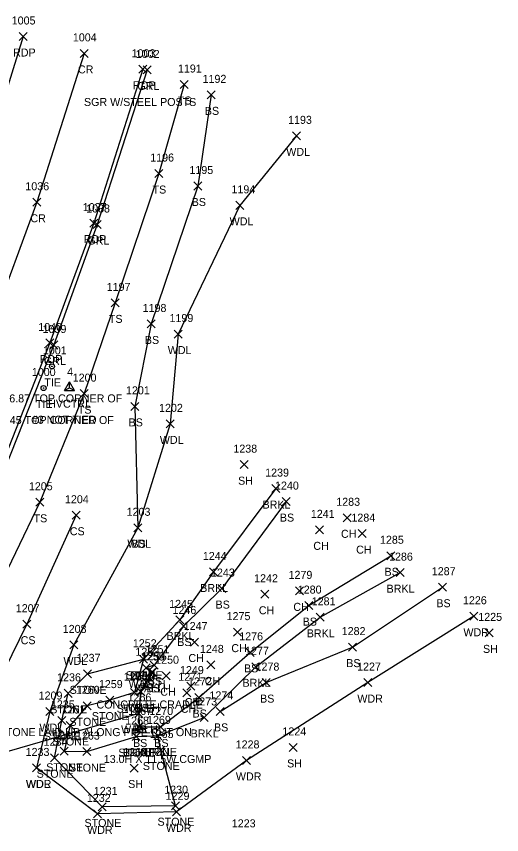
# Model space of a CAD drawing. Extents: x 1599840 to 1601211, y 518904 to 521989.
# Drawn here: x 1600924.1 to 1601045.4, y 521308.1 to 521512.5 of the extents above; entities that cross this region are included whole.
import ezdxf

# ---------------------------------------------------------------- set-up
doc = ezdxf.new("R2010")
doc.units = 0
for name, color, linetype in [('C_A', 7, 'Continuous'), ('C_C', 7, 'Continuous'), ('C_I', 7, 'Continuous'), ('CBP', 7, 'Continuous'), ('CPSM', 7, 'Continuous'), ('D_A', 7, 'Continuous'), ('D_C', 7, 'Continuous'), ('D_I', 7, 'Continuous'), ('D_TIC', 7, 'Continuous'), ('DCP', 7, 'Continuous'), ('DHW', 7, 'Continuous'), ('L_A', 7, 'Continuous'), ('L_C', 7, 'Continuous'), ('L_I', 7, 'Continuous'), ('L_TIC', 7, 'Continuous'), ('LASF', 7, 'Continuous'), ('LAWA', 7, 'Continuous'), ('LAWE', 7, 'Continuous'), ('LELB', 7, 'Continuous'), ('P_A', 7, 'Continuous'), ('P_I', 7, 'Continuous'), ('P_TIC', 7, 'Continuous'), ('PET', 7, 'Continuous'), ('PRC', 7, 'Continuous'), ('R_A', 7, 'Continuous'), ('R_C', 7, 'Continuous'), ('R_I', 7, 'Continuous'), ('R_TIC', 7, 'Continuous'), ('RGR', 7, 'Continuous')]:
    doc.layers.add(name, color=color, linetype=linetype)

msp = doc.modelspace()

# ---------------------------------------------------------------- linework, layer by layer
at = {"layer": 'CBP'}
for centre, radius in [((1600933.05, 521425.11), 0.625), ((1600933.05, 521425.11), 0.0833), ((1600930.95, 521419.7), 0.625), ((1600930.95, 521419.7), 0.0833)]:
    msp.add_circle(centre, radius, dxfattribs=at)
at = {"layer": 'CPSM'}
for p, q in [((1600936.15, 521419.07), (1600937.4, 521421.24)), ((1600938.65, 521419.07), (1600937.4, 521421.24)), ((1600937.4, 521419.79), (1600937.4, 521421.24)), ((1600936.15, 521419.07), (1600937.4, 521419.79)), ((1600936.15, 521419.07), (1600938.65, 521419.07)), ((1600937.4, 521419.79), (1600937.4, 521419.79)), ((1600937.4, 521419.79), (1600938.65, 521419.07))]:
    msp.add_line(p, q, dxfattribs=at)
at = {"layer": 'D_TIC'}
for points in [[(1600955.59, 521348.8), (1600957.59, 521350.8)], [(1600957.59, 521348.8), (1600955.59, 521350.8)], [(1600956.92, 521347.64), (1600958.92, 521349.64)], [(1600958.92, 521347.64), (1600956.92, 521349.64)], [(1600954.19, 521342.91), (1600956.19, 521344.91)], [(1600956.19, 521342.91), (1600954.19, 521344.91)], [(1600953.73, 521337.43), (1600955.73, 521339.43)], [(1600955.73, 521337.43), (1600953.73, 521339.43)], [(1600953.73, 521337.43), (1600955.73, 521339.43)], [(1600955.73, 521337.43), (1600953.73, 521339.43)]]:
    msp.add_lwpolyline(points, dxfattribs=at)
at = {"layer": 'DCP'}
msp.add_lwpolyline([(1600954.73, 521338.43), (1600785.44, 521289.23)], dxfattribs=at)
at = {"layer": 'DHW'}
msp.add_lwpolyline([(1600956.59, 521349.8), (1600957.92, 521348.64), (1600955.19, 521343.91), (1600954.73, 521338.43)], dxfattribs=at)
at = {"layer": 'L_TIC'}
for points in [[(1600965.09, 521494.52), (1600967.09, 521496.52)], [(1600967.09, 521494.52), (1600965.09, 521496.52)], [(1600971.81, 521491.94), (1600973.81, 521493.94)], [(1600973.81, 521491.94), (1600971.81, 521493.94)], [(1600993.18, 521481.7), (1600995.18, 521483.7)], [(1600995.18, 521481.7), (1600993.18, 521483.7)], [(1600958.78, 521472.28), (1600960.78, 521474.28)], [(1600960.78, 521472.28), (1600958.78, 521474.28)], [(1600968.53, 521469.17), (1600970.53, 521471.17)], [(1600970.53, 521469.17), (1600968.53, 521471.17)], [(1600979.04, 521464.34), (1600981.04, 521466.34)], [(1600981.04, 521464.34), (1600979.04, 521466.34)], [(1600947.85, 521439.97), (1600949.85, 521441.97)], [(1600949.85, 521439.97), (1600947.85, 521441.97)], [(1600956.82, 521434.71), (1600958.82, 521436.71)], [(1600958.82, 521434.71), (1600956.82, 521436.71)], [(1600963.56, 521432.18), (1600965.56, 521434.18)], [(1600965.56, 521432.18), (1600963.56, 521434.18)], [(1600940.09, 521417.3), (1600942.09, 521419.3)], [(1600942.09, 521417.3), (1600940.09, 521419.3)], [(1600952.74, 521414.12), (1600954.74, 521416.12)], [(1600954.74, 521414.12), (1600952.74, 521416.12)], [(1600961.58, 521409.75), (1600963.58, 521411.75)], [(1600963.58, 521409.75), (1600961.58, 521411.75)], [(1600980.08, 521399.56), (1600982.08, 521401.56)], [(1600982.08, 521399.56), (1600980.08, 521401.56)], [(1600988.03, 521393.58), (1600990.03, 521395.58)], [(1600990.03, 521393.58), (1600988.03, 521395.58)], [(1600929.04, 521390.16), (1600931.04, 521392.16)], [(1600931.04, 521390.16), (1600929.04, 521392.16)], [(1600990.57, 521390.33), (1600992.57, 521392.33)], [(1600992.57, 521390.33), (1600990.57, 521392.33)], [(1600938.06, 521386.92), (1600940.06, 521388.92)], [(1600940.06, 521386.92), (1600938.06, 521388.92)], [(1601005.79, 521386.28), (1601007.79, 521388.28)], [(1601007.79, 521386.28), (1601005.79, 521388.28)], [(1600953.48, 521383.78), (1600955.48, 521385.78)], [(1600955.48, 521383.78), (1600953.48, 521385.78)], [(1600953.48, 521383.78), (1600955.48, 521385.78)], [(1600955.48, 521383.78), (1600953.48, 521385.78)], [(1600998.88, 521383.27), (1601000.88, 521385.27)], [(1601000.88, 521383.27), (1600998.88, 521385.27)], [(1601009.59, 521382.33), (1601011.59, 521384.33)], [(1601011.59, 521382.33), (1601009.59, 521384.33)], [(1601016.73, 521376.8), (1601018.73, 521378.8)], [(1601018.73, 521376.8), (1601016.73, 521378.8)], [(1600972.45, 521372.75), (1600974.45, 521374.75)], [(1600974.45, 521372.75), (1600972.45, 521374.75)], [(1601019.04, 521372.58), (1601021.04, 521374.58)], [(1601021.04, 521372.58), (1601019.04, 521374.58)], [(1601029.68, 521368.94), (1601031.68, 521370.94)], [(1601031.68, 521368.94), (1601029.68, 521370.94)], [(1600974.49, 521368.6), (1600976.49, 521370.6)], [(1600976.49, 521368.6), (1600974.49, 521370.6)], [(1600985.27, 521367.18), (1600987.27, 521369.18)], [(1600987.27, 521367.18), (1600985.27, 521369.18)], [(1600993.88, 521368.03), (1600995.88, 521370.03)], [(1600995.88, 521368.03), (1600993.88, 521370.03)], [(1600996.25, 521364.35), (1600998.25, 521366.35)], [(1600998.25, 521364.35), (1600996.25, 521366.35)], [(1600964.03, 521360.78), (1600966.03, 521362.78)], [(1600966.03, 521360.78), (1600964.03, 521362.78)], [(1600999.08, 521361.42), (1601001.08, 521363.42)], [(1601001.08, 521361.42), (1600999.08, 521363.42)], [(1601037.52, 521361.68), (1601039.52, 521363.68)], [(1601039.52, 521361.68), (1601037.52, 521363.68)], [(1600925.77, 521359.7), (1600927.77, 521361.7)], [(1600927.77, 521359.7), (1600925.77, 521361.7)], [(1600964.92, 521359.25), (1600966.92, 521361.25)], [(1600966.92, 521359.25), (1600964.92, 521361.25)], [(1600978.38, 521357.72), (1600980.38, 521359.72)], [(1600980.38, 521357.72), (1600978.38, 521359.72)], [(1601041.3, 521357.53), (1601043.3, 521359.53)], [(1601043.3, 521357.53), (1601041.3, 521359.53)], [(1600967.66, 521355.25), (1600969.66, 521357.25)], [(1600969.66, 521355.25), (1600967.66, 521357.25)], [(1600937.5, 521354.53), (1600939.5, 521356.53)], [(1600939.5, 521354.53), (1600937.5, 521356.53)], [(1600981.6, 521352.67), (1600983.6, 521354.67)], [(1600983.6, 521352.67), (1600981.6, 521354.67)], [(1601007.16, 521353.98), (1601009.16, 521355.98)], [(1601009.16, 521353.98), (1601007.16, 521355.98)], [(1600954.94, 521350.95), (1600956.94, 521352.95)], [(1600956.94, 521350.95), (1600954.94, 521352.95)], [(1600954.94, 521350.95), (1600956.94, 521352.95)], [(1600956.94, 521350.95), (1600954.94, 521352.95)], [(1600955.59, 521348.8), (1600957.59, 521350.8)], [(1600957.59, 521348.8), (1600955.59, 521350.8)], [(1600957.57, 521349.46), (1600959.57, 521351.46)], [(1600959.57, 521349.46), (1600957.57, 521351.46)], [(1600971.72, 521349.53), (1600973.72, 521351.53)], [(1600973.72, 521349.53), (1600971.72, 521351.53)], [(1600983.01, 521349.06), (1600985.01, 521351.06)], [(1600985.01, 521349.06), (1600983.01, 521351.06)], [(1600940.92, 521347.3), (1600942.92, 521349.3)], [(1600942.92, 521347.3), (1600940.92, 521349.3)], [(1600957.18, 521347.7), (1600959.18, 521349.7)], [(1600959.18, 521347.7), (1600957.18, 521349.7)], [(1600960.62, 521346.83), (1600962.62, 521348.83)], [(1600962.62, 521346.83), (1600960.62, 521348.83)], [(1600985.62, 521345.11), (1600987.62, 521347.11)], [(1600987.62, 521345.11), (1600985.62, 521347.11)], [(1601011.01, 521345.11), (1601013.01, 521347.11)], [(1601013.01, 521345.11), (1601011.01, 521347.11)], [(1600936.06, 521342.43), (1600938.06, 521344.43)], [(1600938.06, 521342.43), (1600936.06, 521344.43)], [(1600952.67, 521342.61), (1600954.67, 521344.61)], [(1600954.67, 521342.61), (1600952.67, 521344.61)], [(1600954.24, 521342.77), (1600956.24, 521344.77)], [(1600956.24, 521342.77), (1600954.24, 521344.77)], [(1600965.76, 521342.57), (1600967.76, 521344.57)], [(1600967.76, 521342.57), (1600965.76, 521344.57)], [(1600966.74, 521344.24), (1600968.74, 521346.24)], [(1600968.74, 521344.24), (1600966.74, 521346.24)], [(1600946.47, 521340.74), (1600948.47, 521342.74)], [(1600948.47, 521340.74), (1600946.47, 521342.74)], [(1600968.74, 521341.39), (1600970.74, 521343.39)], [(1600970.74, 521341.39), (1600968.74, 521343.39)], [(1600940.84, 521339.31), (1600942.84, 521341.31)], [(1600942.84, 521339.31), (1600940.84, 521341.31)], [(1600931.49, 521337.88), (1600933.49, 521339.88)], [(1600933.49, 521337.88), (1600931.49, 521339.88)], [(1600953.73, 521337.43), (1600955.73, 521339.43)], [(1600955.73, 521337.43), (1600953.73, 521339.43)], [(1600970.06, 521336.4), (1600972.06, 521338.4)], [(1600972.06, 521336.4), (1600970.06, 521338.4)], [(1600974.1, 521337.92), (1600976.1, 521339.92)], [(1600976.1, 521337.92), (1600974.1, 521339.92)], [(1600934.47, 521335.68), (1600936.47, 521337.68)], [(1600936.47, 521335.68), (1600934.47, 521337.68)], [(1600936.57, 521334.4), (1600938.57, 521336.4)], [(1600938.57, 521334.4), (1600936.57, 521336.4)], [(1600953.86, 521334.03), (1600955.86, 521336.03)], [(1600955.86, 521334.03), (1600953.86, 521336.03)], [(1600959.17, 521334.02), (1600961.17, 521336.02)], [(1600961.17, 521334.02), (1600959.17, 521336.02)], [(1600953.08, 521331.61), (1600955.08, 521333.61)], [(1600955.08, 521331.61), (1600953.08, 521333.61)], [(1600953.08, 521331.61), (1600955.08, 521333.61)], [(1600955.08, 521331.61), (1600953.08, 521333.61)], [(1600958.54, 521331.8), (1600960.54, 521333.8)], [(1600960.54, 521331.8), (1600958.54, 521333.8)], [(1600958.54, 521331.8), (1600960.54, 521333.8)], [(1600960.54, 521331.8), (1600958.54, 521333.8)], [(1600959.22, 521328.27), (1600961.22, 521330.27)], [(1600961.22, 521328.27), (1600959.22, 521330.27)], [(1600992.34, 521328.92), (1600994.34, 521330.92)], [(1600994.34, 521328.92), (1600992.34, 521330.92)], [(1600932.66, 521326.34), (1600934.66, 521328.34)], [(1600934.66, 521326.34), (1600932.66, 521328.34)], [(1600935.06, 521327.96), (1600937.06, 521329.96)], [(1600937.06, 521327.96), (1600935.06, 521329.96)], [(1600940.77, 521327.87), (1600942.77, 521329.87)], [(1600942.77, 521327.87), (1600940.77, 521329.87)], [(1600980.65, 521325.67), (1600982.65, 521327.67)], [(1600982.65, 521325.67), (1600980.65, 521327.67)], [(1600928.15, 521323.79), (1600930.15, 521325.79)], [(1600930.15, 521323.79), (1600928.15, 521325.79)], [(1600928.15, 521323.79), (1600930.15, 521325.79)], [(1600930.15, 521323.79), (1600928.15, 521325.79)], [(1600952.6, 521323.77), (1600954.6, 521325.77)], [(1600954.6, 521323.77), (1600952.6, 521325.77)], [(1600944.62, 521314.06), (1600946.62, 521316.06)], [(1600946.62, 521314.06), (1600944.62, 521316.06)], [(1600962.88, 521314.35), (1600964.88, 521316.35)], [(1600964.88, 521314.35), (1600962.88, 521316.35)], [(1600962.88, 521314.35), (1600964.88, 521316.35)], [(1600964.88, 521314.35), (1600962.88, 521316.35)], [(1600943.46, 521312.31), (1600945.46, 521314.31)], [(1600945.46, 521312.31), (1600943.46, 521314.31)], [(1600963.17, 521312.83), (1600965.17, 521314.83)], [(1600965.17, 521312.83), (1600963.17, 521314.83)]]:
    msp.add_lwpolyline(points, dxfattribs=at)
at = {"layer": 'LASF'}
for points in [[(1600963.88, 521315.35), (1600945.62, 521315.06), (1600933.66, 521327.34), (1600935.47, 521336.68), (1600937.06, 521343.43), (1600941.92, 521348.3), (1600955.94, 521351.95), (1600953.67, 521343.61), (1600947.47, 521341.74), (1600941.84, 521340.31), (1600937.57, 521335.4), (1600936.06, 521328.96), (1600941.77, 521328.87), (1600954.08, 521332.61)], [(1600963.88, 521315.35), (1600960.22, 521329.27), (1600959.54, 521332.8)]]:
    msp.add_lwpolyline(points, dxfattribs=at)
at = {"layer": 'LAWA'}
for points in [[(1600994.18, 521482.7), (1600980.04, 521465.34), (1600964.56, 521433.18), (1600962.58, 521410.75), (1600954.48, 521384.78), (1600938.5, 521355.53), (1600932.49, 521338.88), (1600929.15, 521324.79)], [(1601038.52, 521362.68), (1601012.01, 521346.11), (1600981.65, 521326.67), (1600964.17, 521313.83), (1600944.46, 521313.31), (1600929.15, 521324.79)]]:
    msp.add_lwpolyline(points, dxfattribs=at)
at = {"layer": 'LAWE'}
for points in [[(1600989.03, 521394.58), (1600973.45, 521373.75), (1600965.03, 521361.78), (1600955.94, 521351.95)], [(1600954.08, 521332.61), (1600959.54, 521332.8), (1600971.06, 521337.4), (1600984.01, 521350.06), (1601000.08, 521362.42), (1601020.04, 521373.58)]]:
    msp.add_lwpolyline(points, dxfattribs=at)
at = {"layer": 'LELB'}
for points in [[(1600966.09, 521495.52), (1600959.78, 521473.28), (1600948.85, 521440.97), (1600941.09, 521418.3), (1600930.04, 521391.16), (1600917.79, 521365.83), (1600907.01, 521343.38), (1600893.45, 521320.99), (1600884.03, 521297.59), (1600887.61, 521294.19)], [(1600972.81, 521492.94), (1600969.53, 521470.17), (1600957.82, 521435.71), (1600953.74, 521415.12), (1600954.48, 521384.78)], [(1600991.57, 521391.33), (1600975.49, 521369.6), (1600965.92, 521360.25), (1600958.57, 521350.46), (1600956.59, 521349.8), (1600958.18, 521348.7), (1600955.24, 521343.77), (1600954.73, 521338.43), (1600954.86, 521335.03), (1600960.17, 521335.02), (1600969.74, 521342.39), (1600982.6, 521353.67), (1600997.25, 521365.35), (1601017.73, 521377.8)], [(1600939.06, 521387.92), (1600926.77, 521360.7), (1600917.25, 521341.48)], [(1600975.1, 521338.92), (1600986.62, 521346.11), (1601008.16, 521354.98), (1601030.68, 521369.94)]]:
    msp.add_lwpolyline(points, dxfattribs=at)
at = {"layer": 'P_TIC'}
for points in [[(1600924.83, 521506.52), (1600926.83, 521508.52)], [(1600926.83, 521506.52), (1600924.83, 521508.52)], [(1600940.11, 521502.3), (1600942.11, 521504.3)], [(1600942.11, 521502.3), (1600940.11, 521504.3)], [(1600954.79, 521498.34), (1600956.79, 521500.34)], [(1600956.79, 521498.34), (1600954.79, 521500.34)], [(1600928.22, 521465.1), (1600930.22, 521467.1)], [(1600930.22, 521465.1), (1600928.22, 521467.1)], [(1600942.51, 521459.9), (1600944.51, 521461.9)], [(1600944.51, 521459.9), (1600942.51, 521461.9)], [(1600931.49, 521429.95), (1600933.49, 521431.95)], [(1600933.49, 521429.95), (1600931.49, 521431.95)]]:
    msp.add_lwpolyline(points, dxfattribs=at)
at = {"layer": 'PET'}
for points in [[(1600925.83, 521507.52), (1600915.18, 521473.31), (1600903.26, 521440.28), (1600887.48, 521401.44), (1600873.35, 521370.15), (1600860.38, 521343.64), (1600847.93, 521319.69), (1600844.65, 521313.14), (1600836.72, 521299.9), (1600818.79, 521271.51), (1600793.69, 521233.92), (1600774.49, 521208.06), (1600757.09, 521185.54), (1600730.91, 521154.49)], [(1600955.79, 521499.34), (1600943.51, 521460.9), (1600932.49, 521430.95), (1600915.63, 521388.21), (1600902.46, 521359.92), (1600888.21, 521330.27), (1600876.23, 521308.06), (1600874.78, 521305.59), (1600851.3, 521265.61), (1600837.44, 521243.85), (1600825.08, 521225.62), (1600799.95, 521190.82), (1600794.12, 521183.15), (1600773.8, 521157.79), (1600751.79, 521131.81)]]:
    msp.add_lwpolyline(points, dxfattribs=at)
at = {"layer": 'PRC'}
msp.add_lwpolyline([(1600941.11, 521503.3), (1600929.22, 521466.1), (1600917.95, 521435.49), (1600901.05, 521394.76), (1600888.43, 521365.83), (1600873.97, 521336.55), (1600862.78, 521315.41), (1600848.88, 521291.08), (1600831.54, 521262.94), (1600805.42, 521224.44), (1600786.95, 521198.81), (1600768.67, 521175.32), (1600742.32, 521144.02)], dxfattribs=at)
at = {"layer": 'R_TIC'}
for points in [[(1600955.84, 521498.16), (1600957.84, 521500.16)], [(1600957.84, 521498.16), (1600955.84, 521500.16)], [(1600943.35, 521459.55), (1600945.35, 521461.55)], [(1600945.35, 521459.55), (1600943.35, 521461.55)], [(1600932.48, 521429.45), (1600934.48, 521431.45)], [(1600934.48, 521429.45), (1600932.48, 521431.45)]]:
    msp.add_lwpolyline(points, dxfattribs=at)
at = {"layer": 'RGR'}
msp.add_lwpolyline([(1600956.84, 521499.16), (1600944.35, 521460.55), (1600933.48, 521430.45), (1600916.49, 521387.81), (1600903.42, 521359.61), (1600888.96, 521329.85), (1600882.66, 521317.57), (1600880.82, 521311.64), (1600881.59, 521304.98)], dxfattribs=at)

# ---------------------------------------------------------------- texts
at = {"layer": 'C_A'}
for s, p in [('TIE', (1600931.13, 521420.11)), ('TIE', (1600929.03, 521414.7)), ('HVCTRL', (1600932.09, 521414.79))]:
    msp.add_text(s, height=2, dxfattribs=at).set_placement(p)
at = {"layer": 'C_C'}
for s, p in [('TIE DIST=6.87 TOP CORNER OF', (1600909.81, 521416.11)), ('TIE DIST=6.45 TOP CORNER OF', (1600907.71, 521410.7)), ('#3 NOT TIED', (1600928.01, 521410.79))]:
    msp.add_text(s, height=2, dxfattribs=at).set_placement(p)
at = {"layer": 'C_I'}
for s, p in [('1001', (1600930.77, 521428.11)), ('1000', (1600928.01, 521422.7)), ('4', (1600936.83, 521422.79))]:
    msp.add_text(s, height=2, dxfattribs=at).set_placement(p)
at = {"layer": 'D_A'}
for s, p in [('WALLH', (1600952.18, 521344.8)), ('WALLH', (1600953.51, 521343.64)), ('WALLH', (1600950.78, 521338.91)), ('WALLH', (1600950.32, 521333.43)), ('P', (1600954.11, 521333.43))]:
    msp.add_text(s, height=2, dxfattribs=at).set_placement(p)
at = {"layer": 'D_C'}
msp.add_text('CONCRETE CRADLE', height=2, dxfattribs=at).set_placement((1600944.17, 521339.64))
at = {"layer": 'D_I'}
for s, p in [('1253', (1600953.9, 521352.8)), ('1255', (1600955.23, 521351.64)), ('1257', (1600952.5, 521346.91)), ('1266', (1600951.94, 521341.43)), ('1266', (1600951.94, 521341.43))]:
    msp.add_text(s, height=2, dxfattribs=at).set_placement(p)
at = {"layer": 'L_A'}
for s, p in [('TS', (1600964.5, 521490.52)), ('BS', (1600971.25, 521487.94)), ('WDL', (1600991.6, 521477.7)), ('TS', (1600958.19, 521468.28)), ('BS', (1600967.97, 521465.17)), ('WDL', (1600977.46, 521460.34)), ('TS', (1600947.26, 521435.97)), ('BS', (1600956.26, 521430.71)), ('WDL', (1600961.98, 521428.18)), ('TS', (1600939.5, 521413.3)), ('BS', (1600952.18, 521410.12)), ('WDL', (1600960, 521405.75)), ('SH', (1600979.56, 521395.56)), ('BRKL', (1600985.67, 521389.58)), ('TS', (1600928.45, 521386.16)), ('BS', (1600990.01, 521386.33)), ('CS', (1600937.5, 521382.92)), ('CH', (1601005.28, 521382.28)), ('WDL', (1600951.9, 521379.78)), ('BS', (1600952.92, 521379.78)), ('CH', (1600998.36, 521379.27)), ('CH', (1601009.07, 521378.33)), ('BS', (1601016.17, 521372.8)), ('BRKL', (1600970.09, 521368.75)), ('BRKL', (1601016.68, 521368.58)), ('BS', (1601029.12, 521364.94)), ('BS', (1600973.93, 521364.6)), ('CH', (1600984.75, 521363.18)), ('CH', (1600993.37, 521364.03)), ('BS', (1600995.7, 521360.35)), ('BRKL', (1600961.67, 521356.78)), ('BRKL', (1600996.73, 521357.42)), ('WDR', (1601035.88, 521357.68)), ('CS', (1600925.21, 521355.7)), ('BS', (1600964.36, 521355.25)), ('CH', (1600977.87, 521353.72)), ('SH', (1601040.78, 521353.53)), ('CH', (1600967.15, 521351.25)), ('WDL', (1600935.91, 521350.53)), ('BS', (1600981.04, 521348.67)), ('BS', (1601006.6, 521349.98)), ('STONE', (1600951.49, 521346.95)), ('BRKL', (1600952.59, 521346.95)), ('BS', (1600955.03, 521344.8)), ('BS', (1600957.01, 521345.46)), ('CH', (1600971.21, 521345.53)), ('BRKL', (1600980.66, 521345.06)), ('STONE', (1600937.46, 521343.3)), ('BS', (1600956.62, 521343.7)), ('CH', (1600960.11, 521342.83)), ('BS', (1600985.06, 521341.11)), ('WDR', (1601009.37, 521341.11)), ('STONE', (1600932.61, 521338.43)), ('STONE', (1600949.21, 521338.61)), ('BS', (1600953.68, 521338.77)), ('CH', (1600965.24, 521338.57)), ('CH', (1600966.23, 521340.24)), ('STONE', (1600943.01, 521336.74)), ('BS', (1600968.18, 521337.39)), ('STONE', (1600937.38, 521335.31)), ('WDL', (1600929.91, 521333.88)), ('BS', (1600953.17, 521333.43)), ('BRKL', (1600967.7, 521332.4)), ('BS', (1600973.54, 521333.92)), ('STONE', (1600931.01, 521331.68)), ('STONE', (1600933.12, 521330.4)), ('BS', (1600953.3, 521330.03)), ('BS', (1600958.61, 521330.02)), ('STONE', (1600949.63, 521327.61)), ('BRKL', (1600950.73, 521327.61)), ('STONE', (1600955.09, 521327.8)), ('BRKL', (1600956.19, 521327.8)), ('STONE', (1600931.61, 521323.96)), ('STONE', (1600955.76, 521324.27)), ('SH', (1600991.82, 521324.92)), ('STONE', (1600929.21, 521322.34)), ('STONE', (1600937.31, 521323.87)), ('WDR', (1600979.01, 521321.67)), ('WDR', (1600926.51, 521319.79)), ('WDL', (1600926.57, 521319.79)), ('SH', (1600952.09, 521319.77)), ('STONE', (1600941.17, 521310.06)), ('STONE', (1600959.43, 521310.35)), ('STONE', (1600959.43, 521310.35)), ('WDR', (1600941.82, 521308.31)), ('WDR', (1600961.53, 521308.83))]:
    msp.add_text(s, height=2, dxfattribs=at).set_placement(p)
at = {"layer": 'L_C'}
for s, p in [('STONE LAID UP ALONG PIPE CUT ON', (1600919.73, 521332.74)), ('13.0H X 11.5W CGMP', (1600945.99, 521326.02))]:
    msp.add_text(s, height=2, dxfattribs=at).set_placement(p)
at = {"layer": 'L_I'}
for s, p in [('1191', (1600964.53, 521498.52)), ('1192', (1600970.68, 521495.94)), ('1193', (1600992.06, 521485.7)), ('1196', (1600957.6, 521476.28)), ('1195', (1600967.4, 521473.17)), ('1194', (1600977.91, 521468.34)), ('1197', (1600946.72, 521443.97)), ('1198', (1600955.7, 521438.71)), ('1199', (1600962.42, 521436.18)), ('1200', (1600938.23, 521421.3)), ('1201', (1600951.54, 521418.12)), ('1202', (1600959.81, 521413.75)), ('1238', (1600978.38, 521403.56)), ('1239', (1600986.33, 521397.58)), ('1205', (1600927.27, 521394.16)), ('1240', (1600988.79, 521394.33)), ('1204', (1600936.29, 521390.92)), ('1283', (1601004.1, 521390.28)), ('1203', (1600951.71, 521387.78)), ('1203', (1600951.71, 521387.78)), ('1241', (1600997.75, 521387.27)), ('1284', (1601007.89, 521386.33)), ('1285', (1601015.03, 521380.8)), ('1244', (1600970.75, 521376.75)), ('1286', (1601017.29, 521376.58)), ('1243', (1600972.79, 521372.6)), ('1242', (1600983.57, 521371.18)), ('1279', (1600992.18, 521372.03)), ('1287', (1601027.98, 521372.94)), ('1280', (1600994.48, 521368.35)), ('1281', (1600997.96, 521365.42)), ('1226', (1601035.77, 521365.68)), ('1207', (1600924, 521363.7)), ('1245', (1600962.34, 521364.78)), ('1246', (1600963.17, 521363.25)), ('1275', (1600976.69, 521361.72)), ('1225', (1601039.6, 521361.53)), ('1247', (1600965.97, 521359.25)), ('1208', (1600935.73, 521358.53)), ('1276', (1600979.85, 521356.67)), ('1282', (1601005.46, 521357.98)), ('1252', (1600953.25, 521354.95)), ('1252', (1600953.25, 521354.95)), ('1253', (1600953.9, 521352.8)), ('1251', (1600956.44, 521353.46)), ('1248', (1600970.03, 521353.53)), ('1277', (1600981.32, 521353.06)), ('1237', (1600939.23, 521351.3)), ('1254', (1600955.49, 521351.7)), ('1250', (1600958.84, 521350.83)), ('1278', (1600983.93, 521349.11)), ('1227', (1601009.31, 521349.11)), ('1236', (1600934.32, 521346.43)), ('1258', (1600950.98, 521346.61)), ('1256', (1600952.5, 521346.77)), ('1271', (1600964.63, 521346.57)), ('1249', (1600965.04, 521348.24)), ('1259', (1600944.77, 521344.74)), ('1272', (1600967.04, 521345.39)), ('1260', (1600939.01, 521343.31)), ('1209', (1600929.71, 521341.88)), ('1266', (1600951.94, 521341.43)), ('1273', (1600968.36, 521340.4)), ('1274', (1600972.41, 521341.92)), ('1235', (1600932.78, 521339.68)), ('1261', (1600935.4, 521338.4)), ('1267', (1600952.12, 521338.03)), ('1270', (1600957.39, 521338.02)), ('1268', (1600951.34, 521335.61)), ('1268', (1600951.34, 521335.61)), ('1269', (1600956.8, 521335.8)), ('1269', (1600956.8, 521335.8)), ('1265', (1600957.48, 521332.27)), ('1224', (1600990.64, 521332.92)), ('1234', (1600930.97, 521330.34)), ('1262', (1600933.32, 521331.96)), ('1263', (1600939.03, 521331.87)), ('1228', (1600978.96, 521329.67)), ('1233', (1600926.46, 521327.79)), ('1233', (1600926.46, 521327.79)), ('1264', (1600950.86, 521327.77)), ('1231', (1600943.5, 521318.06)), ('1230', (1600961.1, 521318.35)), ('1230', (1600961.1, 521318.35)), ('1232', (1600941.76, 521316.31)), ('1229', (1600961.46, 521316.83)), ('1223', (1600977.99, 521309.95))]:
    msp.add_text(s, height=2, dxfattribs=at).set_placement(p)
at = {"layer": 'P_A'}
for s, p in [('RDP', (1600923.32, 521502.52)), ('CR', (1600939.54, 521498.3)), ('RDP', (1600953.28, 521494.34)), ('CR', (1600927.65, 521461.1)), ('RDP', (1600941, 521455.9)), ('RDP', (1600929.98, 521425.95))]:
    msp.add_text(s, height=2, dxfattribs=at).set_placement(p)
at = {"layer": 'P_I'}
for s, p in [('1005', (1600922.98, 521510.52)), ('1004', (1600938.26, 521506.3)), ('1003', (1600952.94, 521502.34)), ('1036', (1600926.39, 521469.1)), ('1037', (1600940.74, 521463.9)), ('1040', (1600929.63, 521433.95))]:
    msp.add_text(s, height=2, dxfattribs=at).set_placement(p)
at = {"layer": 'R_A'}
for p in [(1600954.38, 521494.16), (1600941.89, 521455.55), (1600931.03, 521425.45)]:
    msp.add_text('GRL', height=2, dxfattribs=at).set_placement(p)
at = {"layer": 'R_C'}
msp.add_text('SGR W/STEEL POSTS', height=2, dxfattribs=at).set_placement((1600941.04, 521490.16))
at = {"layer": 'R_I'}
for s, p in [('1002', (1600953.99, 521502.16)), ('1038', (1600941.58, 521463.55)), ('1039', (1600930.7, 521433.45))]:
    msp.add_text(s, height=2, dxfattribs=at).set_placement(p)

doc.saveas('drawing.dxf')
